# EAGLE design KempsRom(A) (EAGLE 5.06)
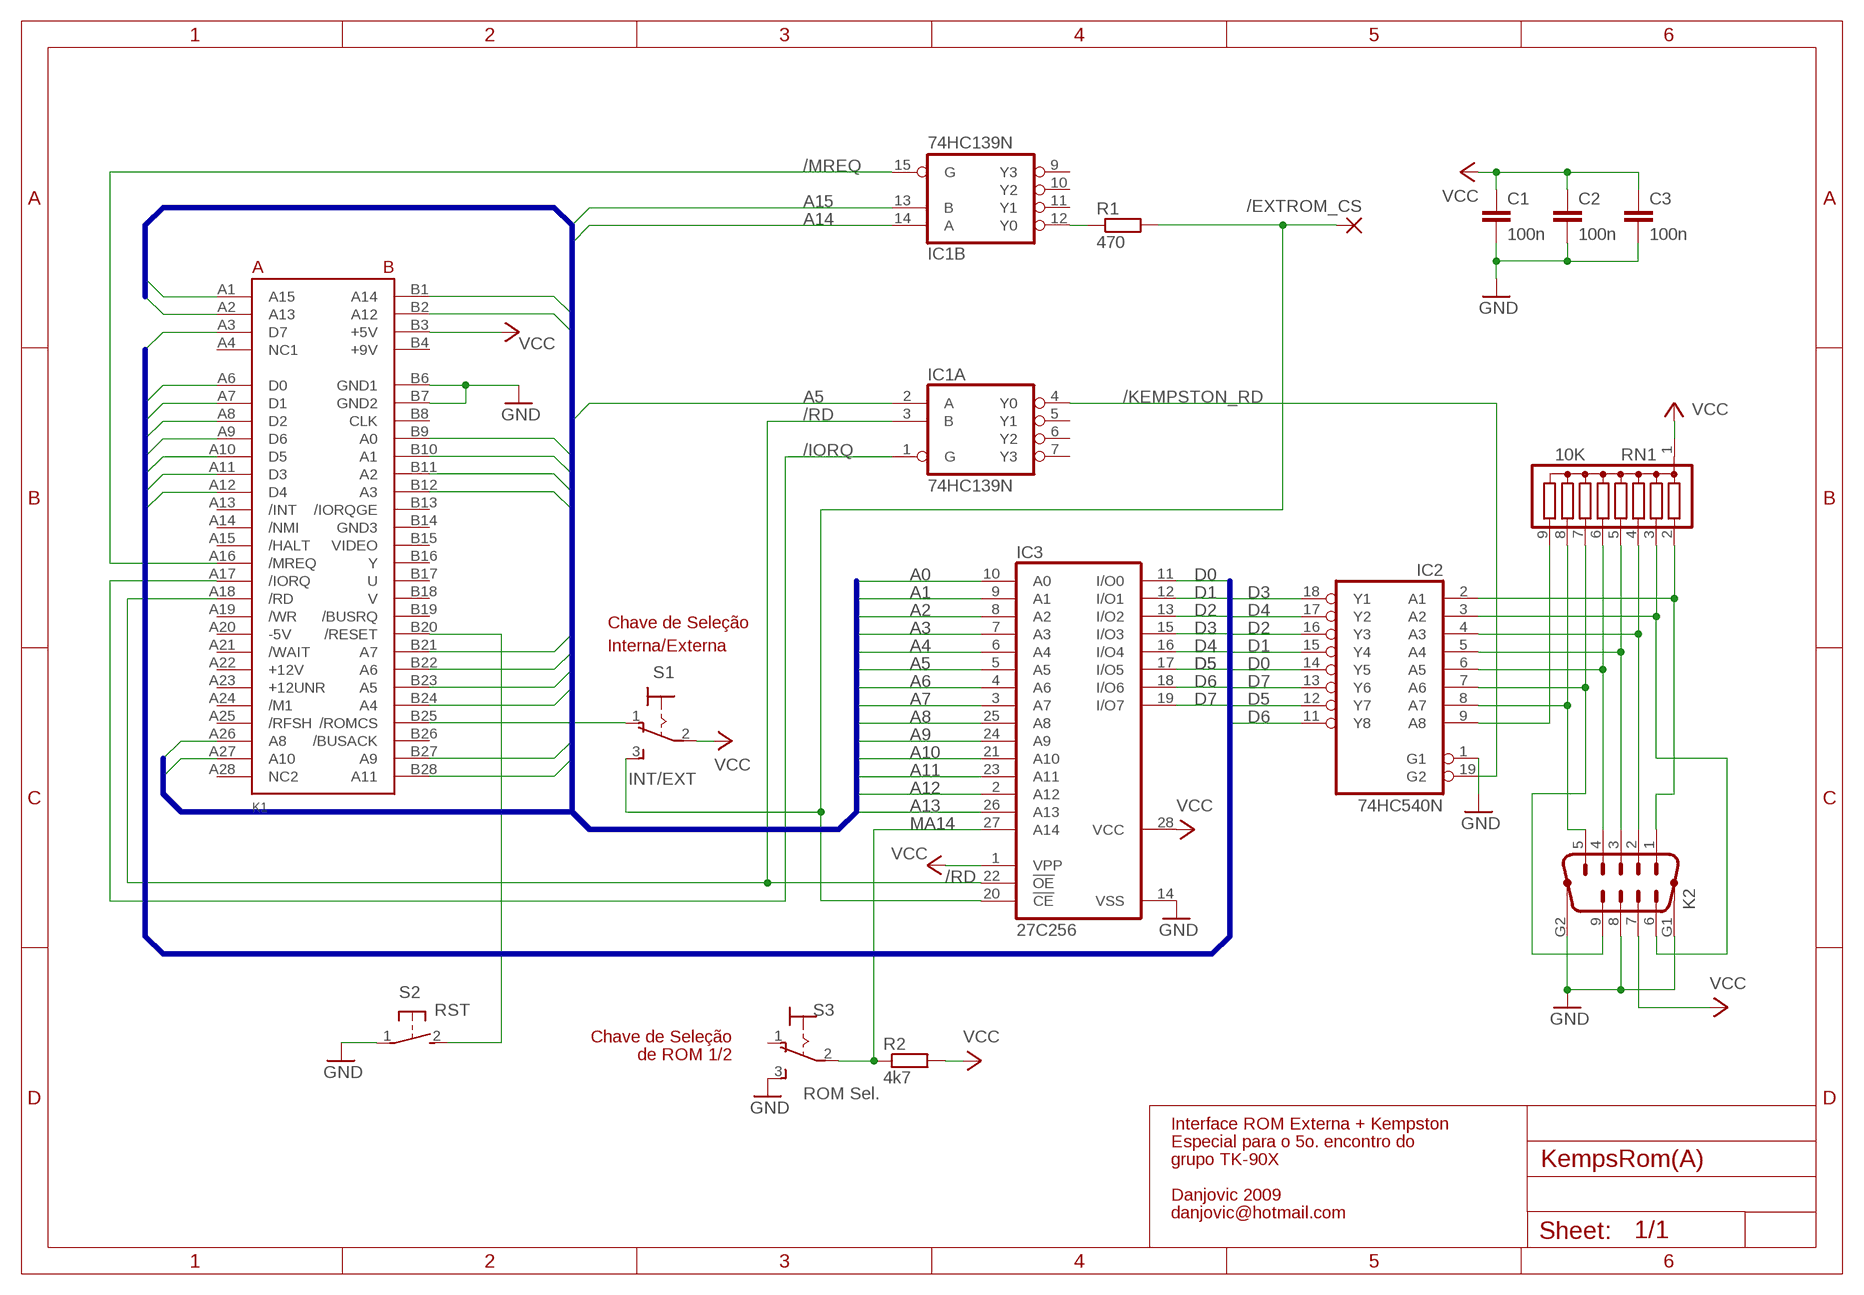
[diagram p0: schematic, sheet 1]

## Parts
/EXTROM_CS  1,6/0,8  [1,6/0,8]
C1  100n  C-EU050-025X075  [C050-025X075]
C2  100n  C-EU050-025X075  [C050-025X075]
C3  100n  C-EU050-025X075  [C050-025X075]
IC1  74HC139N  [DIL16]
IC2  74HC540N  [DIL20]
IC3  27C256  27C256AG  [DIL28-6]
K1  ZX-EDGE  [ZX-DIL]
K2  M09HP  [M09HP]
R1  470  R-EU_0204/7  [0204/7]
R2  4k7  R-EU_0204/7  [0204/7]
RN1  10K  G08R  [SIL9]
S1  INT/EXT  320-916  [320-916]
S2  RST  31-XX  [B3F-31XX]
S3  ROM Sel.  320-916  [320-916]

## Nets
/EXTROM_CS: /EXTROM_CS.1(P) IC3.20(!CE) R1.2 S1.3(S)
/IORQ: IC1.1(A:G) K1.A17(/IORQ)
/KEMPSTON_RD: IC1.4(A:Y0) IC2.19(G2)
/MREQ: IC1.15(B:G) K1.A16(/MREQ)
/RD: IC1.3(A:B) IC3.22(!OE) K1.A18(/RD)
/RESET: K1.B20(/RESET) S2.2(S)
/ROMCS: K1.B25(/ROMCS) S1.1(O)
A0: IC3.10(A0) K1.B9(A0)
A1: IC3.9(A1) K1.B10(A1)
A2: IC3.8(A2) K1.B11(A2)
A3: IC3.7(A3) K1.B12(A3)
A4: IC3.6(A4) K1.B24(A4)
A5: IC1.2(A:A) IC3.5(A5) K1.B23(A5)
A6: IC3.4(A6) K1.B22(A6)
A7: IC3.3(A7) K1.B21(A7)
A8: IC3.25(A8) K1.A26(A8)
A9: IC3.24(A9) K1.B27(A9)
A10: IC3.21(A10) K1.A27(A10)
A11: IC3.23(A11) K1.B28(A11)
A12: IC3.2(A12) K1.B2(A12)
A13: IC3.26(A13) K1.A2(A13)
A14: IC1.14(B:A) K1.B1(A14)
A15: IC1.13(B:B) K1.A1(A15)
D0: IC2.14(Y5) IC3.11(I/O0) K1.A6(D0)
D1: IC2.15(Y4) IC3.12(I/O1) K1.A7(D1)
D2: IC2.16(Y3) IC3.13(I/O2) K1.A8(D2)
D3: IC2.18(Y1) IC3.15(I/O3) K1.A11(D3)
D4: IC2.17(Y2) IC3.16(I/O4) K1.A12(D4)
D5: IC2.12(Y7) IC3.17(I/O5) K1.A10(D5)
D6: IC2.11(Y8) IC3.18(I/O6) K1.A9(D6)
D7: IC2.13(Y6) IC3.19(I/O7) K1.A3(D7)
GND: C1.2 C2.2 C3.2 IC2.1(G1) IC3.14(VSS) K1.B6(GND1) K1.B7(GND2) K2.8 K2.G1 K2.G2 S2.1(P) S3.3(S)
MA14: IC3.27(A14) R2.1 S3.2(P)
N$1: IC2.2(A1) K2.1 RN1.2
N$2: IC1.12(B:Y0) R1.1
N$4: IC2.3(A2) K2.6 RN1.3
N$5: IC2.4(A3) K2.2 RN1.4
N$6: IC2.5(A4) K2.3 RN1.5
N$7: IC2.6(A5) K2.4 RN1.6
N$8: IC2.7(A6) K2.9 RN1.7
N$9: IC2.8(A7) K2.5 RN1.8
N$10: IC2.9(A8) RN1.9
VCC: C1.1 C2.1 C3.1 IC3.1(VPP) IC3.28(VCC) K1.B3(+5V) K2.7 R2.2 RN1.1 S1.2(P)
Unconnected: IC1.5(A:Y1) IC1.6(A:Y2) IC1.7(A:Y3) IC1.9(B:Y3) IC1.10(B:Y2) IC1.11(B:Y1) K1.A4(NC1) K1.A13(/INT) K1.A14(/NMI) K1.A15(/HALT) K1.A19(/WR) K1.A20(-5V) K1.A21(/WAIT) K1.A24(/M1) K1.A25(/RFSH) K1.A28(NC2) K1.B8(CLK) K1.B13(/IORQGE) K1.B14(GND3) K1.B15(VIDEO) K1.B16(Y) K1.B17(U) K1.B18(V) K1.B19(/BUSRQ) K1.B26(/BUSACK) S3.1(O)

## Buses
A[0..15]
D[0..7]

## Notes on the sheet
- Chave de Seleção
- Interna/Externa
- Chave de Seleção
- de ROM 1/2
- Interface ROM Externa + Kempston
- Especial para o 5o. encontro do
- grupo TK-90X
- Danjovic 2009
- danjovic@hotmail.com

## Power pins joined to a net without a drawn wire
+9V: K1.B4(+9V)
+12UNR: K1.A23(+12UNR)
+12V: K1.A22(+12V)
GND: IC1.8(P:GND) IC2.10(GND)
VCC: IC1.16(P:VCC) IC2.20(VCC)

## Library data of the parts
/EXTROM_CS = wirepad:1,6/0,8: THROUGH-HOLE PAD
C1-C3 = rcl:C-EU: CAPACITOR, European symbol
IC1 = 74xx-eu:74*139: Dual 2-line to 4-line DECODER/DEMULTIPLEXER
IC2 = 74xx-eu:74*540: Octal BUFFER and LINE DRIVER, 3-state
IC3 = memory-hitachi:27C256AG: MEMORY
K1 = diversos2:ZX-EDGE: ZX Spectrum Rear edge connector
K2 = con-subd:M09HP: SUB-D
R1 R2 = rcl:R-EU_: RESISTOR, European symbol
RN1 = resistor-sil:G08R: SIL RESISTOR
S1 S3 = switch:320-916: TOGGLE SWITCH distributor RS Components
S2 = switch-omron:31-XX: OMRON SWITCH

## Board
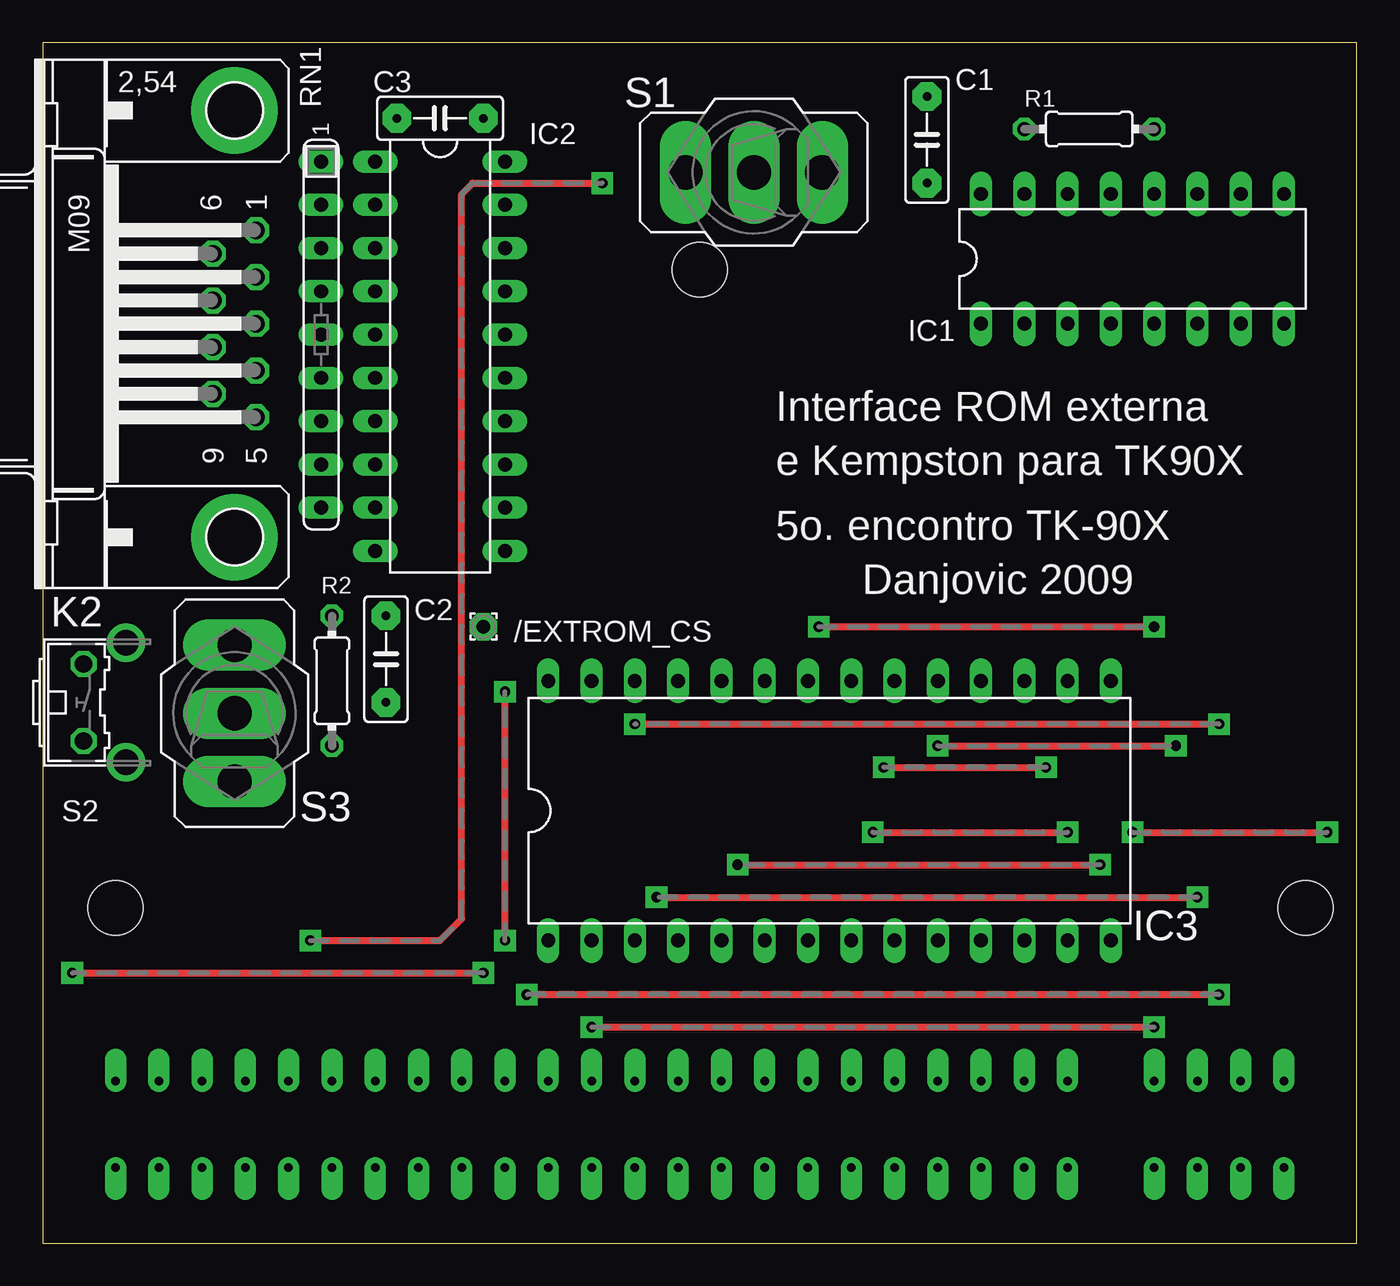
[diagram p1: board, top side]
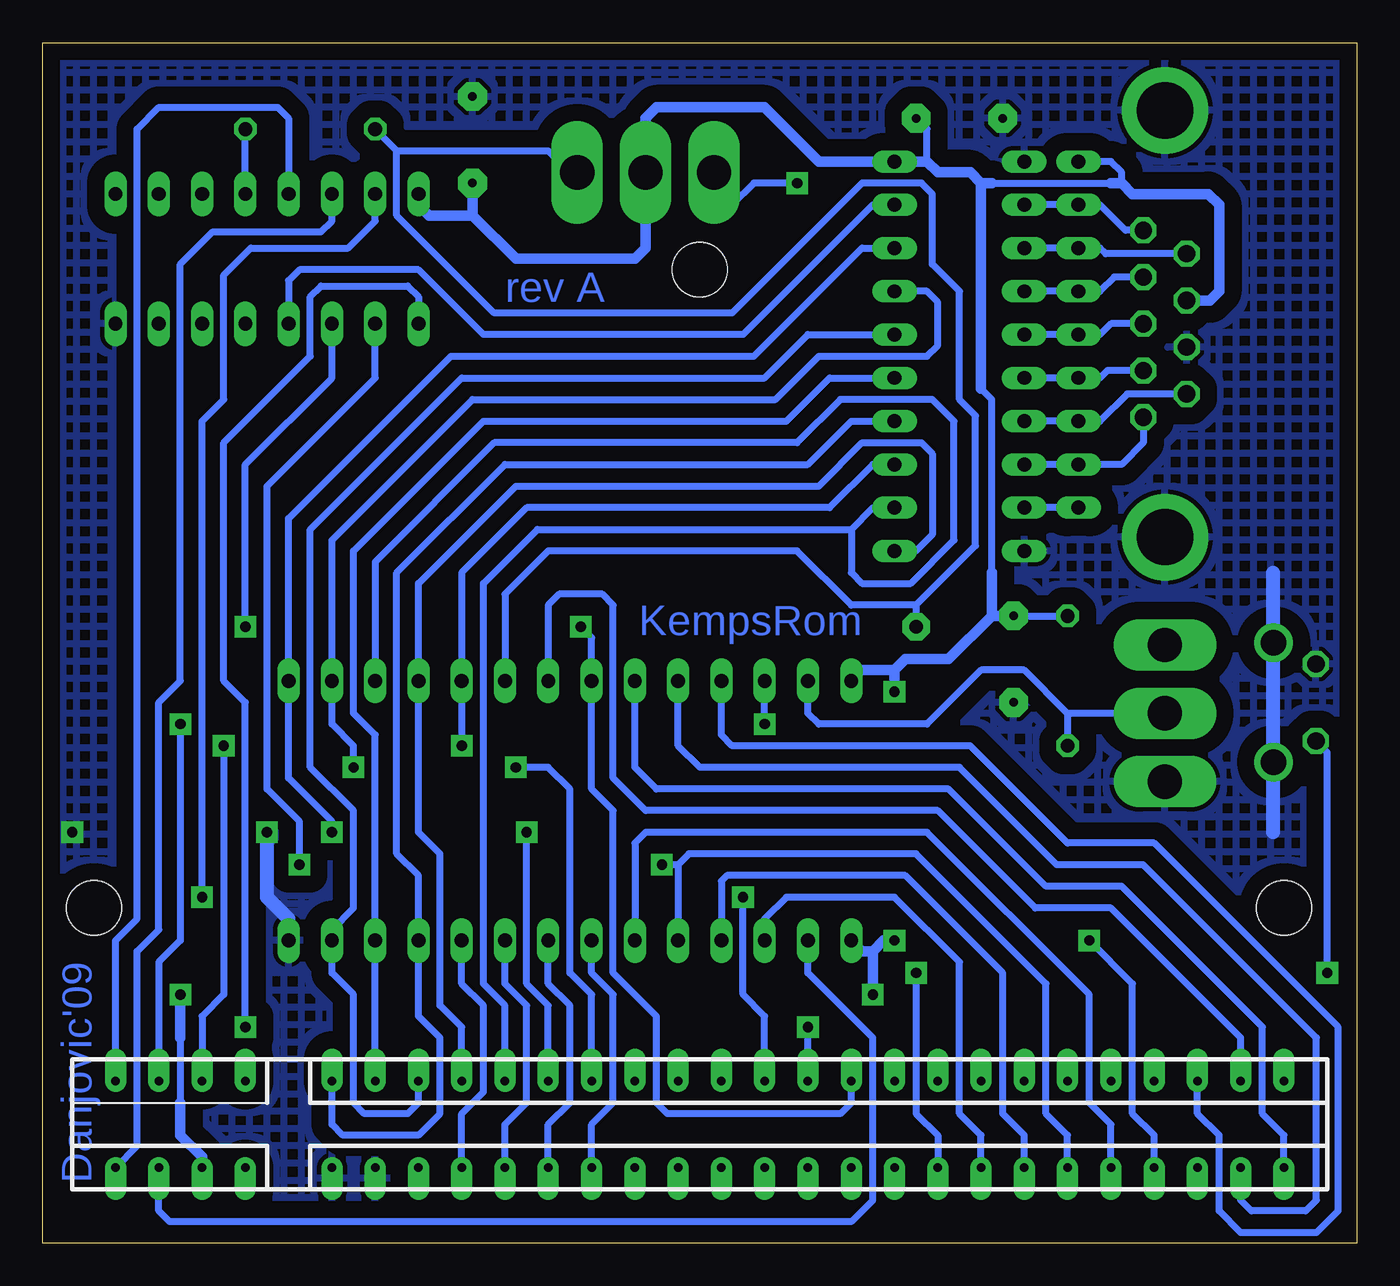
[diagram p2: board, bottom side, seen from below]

Size 77.14 x 70.47 mm. Coordinates in mm from the lower left corner, seen from the top.
Outline: 0,0 77.14,0 77.14,70.47 0,70.47 0,0
Copper layers (1*16): Top 0.035mm / dielectric 1.5mm / Bottom 0.035mm
Design rules "default": minimum track width 10mil, minimum drill 24mil, track to track 8mil, track to pad 8mil, pad to pad 8mil, via to via 8mil, smd to smd 8mil, copper to edge 40mil, drill to drill 8mil, minimum pad ring 10mil, minimum via ring 8mil, stop-mask expansion 4mil, vias tented up to drill 0mil, thermal gap 10mil
Holes 3.2 mm at 4.28,19.68 74.13,19.68 38.57,57.15

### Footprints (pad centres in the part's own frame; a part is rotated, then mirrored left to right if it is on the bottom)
1,6/0,8 = drill 0.813 pad 1.6 octagon: 1 0,0
C050-025X075 = drill 0.5 pad 1.676 octagon: 1 -2.54,0; 2 2.54,0
DIL16 = drill 0.813 long: 1 -8.89,-3.81; 2 -6.35,-3.81; 3 -3.81,-3.81; 4 -1.27,-3.81; 5 1.27,-3.81; 6 3.81,-3.81; 7 6.35,-3.81; 8 8.89,-3.81; 9 8.89,3.81; 10 6.35,3.81; 11 3.81,3.81; 12 1.27,3.81; 13 -1.27,3.81; 14 -3.81,3.81; 15 -6.35,3.81; 16 -8.89,3.81
DIL20 = drill 0.813 long: 1 -11.43,-3.81; 2 -8.89,-3.81; 3 -6.35,-3.81; 4 -3.81,-3.81; 5 -1.27,-3.81; 6 1.27,-3.81; 7 3.81,-3.81; 8 6.35,-3.81; 9 8.89,-3.81; 10 11.43,-3.81; 11 11.43,3.81; 12 8.89,3.81; 13 6.35,3.81; 14 3.81,3.81; 15 1.27,3.81; 16 -1.27,3.81; 17 -3.81,3.81; 18 -6.35,3.81; 19 -8.89,3.81; 20 -11.43,3.81
DIL28-6 = drill 0.813 long: 1 -16.51,-7.62; 2 -13.97,-7.62; 3 -11.43,-7.62; 4 -8.89,-7.62; 5 -6.35,-7.62; 6 -3.81,-7.62; 7 -1.27,-7.62; 8 1.27,-7.62; 9 3.81,-7.62; 10 6.35,-7.62; 11 8.89,-7.62; 12 11.43,-7.62; 13 13.97,-7.62; 14 16.51,-7.62; 15 16.51,7.62; 16 13.97,7.62; 17 11.43,7.62; 18 8.89,7.62; 19 6.35,7.62; 20 3.81,7.62; 21 1.27,7.62; 22 -1.27,7.62; 23 -3.81,7.62; 24 -6.35,7.62; 25 -8.89,7.62; 26 -11.43,7.62; 27 -13.97,7.62; 28 -16.51,7.62
ZX-DIL = drill 0.5 pad 1.27 offset: A1 2.54,33.02; A2 2.54,30.48; A3 2.54,27.94; A4 2.54,25.4; A6 2.54,20.32; A7 2.54,17.78; A8 2.54,15.24; A9 2.54,12.7; A10 2.54,10.16; A11 2.54,7.62; A12 2.54,5.08; A13 2.54,2.54; A14 2.54,0; A15 2.54,-2.54; A16 2.54,-5.08; A17 2.54,-7.62; A18 2.54,-10.16; A19 2.54,-12.7; A20 2.54,-15.24; A21 2.54,-17.78; A22 2.54,-20.32; A23 2.54,-22.86; A24 2.54,-25.4; A25 2.54,-27.94; A26 2.54,-30.48; A27 2.54,-33.02; A28 2.54,-35.56; B1 -2.54,33.02; B2 -2.54,30.48; B3 -2.54,27.94; B4 -2.54,25.4; B6 -2.54,20.32; B7 -2.54,17.78; B8 -2.54,15.24; B9 -2.54,12.7; B10 -2.54,10.16; B11 -2.54,7.62; B12 -2.54,5.08; B13 -2.54,2.54; B14 -2.54,0; B15 -2.54,-2.54; B16 -2.54,-5.08; B17 -2.54,-7.62; B18 -2.54,-10.16; B19 -2.54,-12.7; B20 -2.54,-15.24; B21 -2.54,-17.78; B22 -2.54,-20.32; B23 -2.54,-22.86; B24 -2.54,-25.4; B25 -2.54,-27.94; B26 -2.54,-30.48; B27 -2.54,-33.02; B28 -2.54,-35.56
M09HP = drill 1.016 octagon: 1 -5.486,1.27; 2 -2.743,1.27; 3 0,1.27; 4 2.743,1.27; 5 5.486,1.27; 6 -4.115,-1.27; 7 -1.372,-1.27; 8 1.372,-1.27; 9 4.115,-1.27 | drill 3.302 pad 5.08 round: G1 -12.522,0; G2 12.522,0
0204/7 = drill 0.813 octagon: 1 -3.81,0; 2 3.81,0
SIL9 = drill 0.813 long: 1 -10.16,0; 2 -7.62,0; 3 -5.08,0; 4 -2.54,0; 5 0,0; 6 2.54,0; 7 5.08,0; 8 7.62,0; 9 10.16,0
320-916 = drill 2.007 long: 1 0,4.013; 2 0,0; 3 0,-4.013
B3F-31XX = drill 1.016 octagon: 1 -2.261,-1.245; 2 2.261,-1.245 | drill 1.499 pad 2.159 round: 3 -3.505,1.245; 4 3.505,1.245

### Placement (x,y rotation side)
/EXTROM_CS  25.87,36.19 0 top
C1  51.91,64.77 90 top
C2  20.16,34.29 270 top
C3  23.33,66.03 180 top
IC1  63.97,57.78 0 top
IC2  23.33,52.07 270 top
IC3  46.19,25.39 0 top
K1  39.84,6.98 90 bottom
K2  11.26,53.97 270 top
R1  61.43,65.4 180 top
R2  16.98,33.02 90 top
RN1  16.34,53.34 270 top
S1  41.75,62.86 90 top
S2  3.64,31.74 270 top
S3  11.26,31.11 0 top

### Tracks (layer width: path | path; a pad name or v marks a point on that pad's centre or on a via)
/EXTROM_CS
  Bottom 0.406: IC3.20 50,38.1 47.46,40.64 32.86,40.64 29.68,37.46 25.87,37.46 | 25.87,37.46 22.38,40.95 22.38,48.57 23.33,49.53 23.33,55.88 24.92,57.46 24.92,61.59 25.55,62.23 29.05,62.23 36.66,54.61 50.63,54.61 56.35,60.32 56.35,64.13 | 56.35,64.13 R1.2 | 56.35,64.13 47.46,64.13 45.76,62.43 S1.3 | 25.87,37.46 /EXTROM_CS.1
/IORQ  (via drill 0.6 pad 1.27)
  Top 0.406: v32.22,12.7 v65.24,12.7
  Bottom 0.406: K1.A17 v32.22,12.7 | v65.24,12.7 65.24,31.74 66.51,33.02 66.51,46.98 61.43,52.07 61.43,55.56 60.79,56.19 55.72,56.19 55.08,55.56 IC1.1
/KEMPSTON_RD
  Bottom 0.406: IC1.4 62.7,56.51 62.07,57.15 55.08,57.15 51.27,53.34 36.03,53.34 28.41,60.96 IC2.19
/MREQ  (via drill 0.6 pad 1.27)
  Top 0.406: v36.03,20.31 v67.78,20.31
  Bottom 0.406: K1.A16 34.76,13.33 36.03,14.6 v36.03,20.31 | v67.78,20.31 67.78,48.26 66.51,49.53 66.51,56.83 64.92,58.41 59.21,58.41 57.62,60 IC1.15
/RD  (via drill 0.6 pad 1.27)
  Top 0.406: v45.55,36.19 v65.24,36.19
  Bottom 0.406: 29.68,10.16 K1.A18 29.68,8.25 30.32,7.62 40.48,7.62 41.11,8.25 41.11,13.33 43.65,15.87 43.65,25.39 44.92,26.66 IC3.22 44.92,35.55 v45.55,36.19 | IC1.3 60.16,50.8 65.24,45.72 v65.24,36.19
/RESET  (via drill 0.6 pad 1.27)
  Top 0.406: v1.74,15.87 v25.87,15.87
  Bottom 0.406: S2.2 1.74,28.82 v1.74,15.87 | v25.87,15.87 25.87,7.62 24.6,6.34 K1.B20
/ROMCS  (via drill 0.6 pad 1.27)
  Top 0.406: v15.71,17.77 23.33,17.77 24.6,19.04 24.6,61.59 25.23,62.23 v32.86,62.23
  Bottom 0.406: K1.B25 11.9,6.34 13.17,7.62 13.17,15.24 v15.71,17.77 | v32.86,62.23 35.4,62.23 36.66,60.96 37.94,60.96 37.73,61.16 S1.1
A0
  Bottom 0.406: K1.B9 52.54,7.62 51.27,8.89 51.27,13.97 52.54,15.24 IC3.10
A1
  Bottom 0.406: K1.B10 50,6.98 48.73,8.25 48.73,13.97 50,15.24 IC3.9
A2
  Bottom 0.406: K1.B11 47.46,6.98 46.19,8.25 46.19,13.97 47.46,15.24 IC3.8
A3
  Bottom 0.406: K1.B12 44.92,6.98 43.65,8.25 43.65,14.6 44.92,15.87 IC3.7
A4
  Bottom 0.406: K1.B24 14.44,6.98 15.71,8.25 15.71,14.6 25.23,24.12 41.75,24.12 42.38,23.49 IC3.6
A5  (via drill 0.6 pad 1.27)
  Top 0.406: v40.79,22.22 v62.07,22.22
  Bottom 0.406: K1.B23 16.98,6.34 18.25,7.62 18.25,15.24 25.87,22.86 39.2,22.86 39.84,22.22 | IC1.2 57.62,50.8 63.97,44.45 63.97,26.66 62.07,24.76 v62.07,22.22 | 39.84,22.22 IC3.5 | 39.84,22.22 v40.79,22.22
A6
  Bottom 0.406: IC3.4 37.3,21.27 36.98,21.58 26.51,21.58 20.79,15.87 20.79,7.62 19.52,6.34 K1.B22
A7
  Bottom 0.406: K1.B21 22.06,6.34 23.33,7.62 23.33,16.5 27.14,20.31 33.49,20.31 34.76,19.04 IC3.3
A8
  Bottom 0.406: K1.A26 9.36,7.62 8.09,6.34 8.09,1.9 6.82,0.63 2.38,0.63 1.11,1.9 1.11,12.7 11.9,23.49 16.98,23.49 22.7,29.2 36.66,29.2 37.3,29.84 IC3.25
A9
  Bottom 0.406: IC3.24 39.84,29.2 38.57,27.93 23.33,27.93 17.62,22.22 12.53,22.22 2.38,12.06 2.38,2.54 3.01,1.9 6.19,1.9 6.82,2.54 K1.B27
A10
  Bottom 0.406: K1.A27 6.82,12.06 14.44,19.68 18.88,19.68 24.6,25.39 41.75,25.39 43.65,27.3 43.65,37.46 44.29,38.1 46.83,38.1 47.46,37.46 IC3.21
A11
  Bottom 0.406: IC3.23 42.38,27.93 41.11,26.66 23.96,26.66 18.25,20.95 13.8,20.95 5.55,12.7 5.55,7.62 4.28,6.34 K1.B28
A12
  Bottom 0.406: K1.B2 70.32,1.9 69.68,1.27 29.68,1.27 28.41,2.54 28.41,12.06 32.22,15.87 IC3.2
A13  (via drill 0.6 pad 1.27)
  Top 0.406: v34.76,30.47 v69.05,30.47
  Bottom 0.406: v69.05,30.47 69.05,17.77 70.32,16.5 K1.A2 | v34.76,30.47 IC3.26
A14
  Bottom 0.406: K1.B1 71.59,5.71 71.59,17.14 70.32,18.41 70.32,31.74 69.05,33.02 69.05,57.46 67.14,59.37 60.79,59.37 60.16,60 IC1.14
A15
  Bottom 0.406: K1.A1 72.86,17.77 71.59,19.04 71.59,65.4 70.32,66.67 63.34,66.67 62.7,66.03 IC1.13
D0
  Bottom 0.406: IC2.14 29.68,48.26 32.22,45.72 50,45.72 56.35,39.37 56.35,22.86 55.08,21.58 IC3.11 55.08,13.33 53.81,12.06 53.81,7.62 55.08,6.34 59.52,6.34 60.16,6.98 K1.A6
D1
  Bottom 0.406: IC2.15 30.95,50.8 33.49,48.26 51.27,48.26 58.89,40.64 58.89,31.11 57.62,29.84 IC3.12 K1.A7
D2
  Bottom 0.406: IC2.16 32.22,53.34 34.76,50.8 52.54,50.8 61.43,41.91 61.43,27.93 58.89,25.39 58.89,19.68 60.16,18.41 IC3.13 60.16,15.87 58.89,14.6 58.89,8.25 58.26,7.62 55.72,7.62 55.08,8.25 K1.A8
D3  (via drill 0.6 pad 1.27)
  Top 0.406: v48.73,24.12 v60.16,24.12
  Bottom 0.406: IC2.18 29.05,58.41 35.4,52.07 53.18,52.07 62.7,42.54 IC3.15 62.7,27.3 60.16,24.76 v60.16,24.12 | K1.A11 47.46,13.97 48.73,15.24 v48.73,24.12
D4  (via drill 0.6 pad 1.27)
  Top 0.406: v49.37,27.93 v58.89,27.93
  Bottom 0.406: IC2.17 25.23,55.88 24.6,55.24 24.6,52.7 25.23,52.07 31.59,52.07 34.12,49.53 51.91,49.53 60.16,41.27 IC3.16 60.16,30.47 58.89,29.2 v58.89,27.93 | K1.A12 44.92,14.6 46.19,15.87 46.19,26.66 47.46,27.93 v49.37,27.93
D5
  Bottom 0.406: 29.68,41.91 29.68,39.37 29.05,38.73 26.19,38.73 23.65,41.27 23.65,48.26 24.92,49.53 30.32,49.53 32.86,46.98 50.63,46.98 57.62,40 IC3.17 | K1.A10 50,13.97 51.27,15.24 51.27,38.73 48.09,41.91 29.68,41.91 | 29.68,41.91 28.41,43.18 IC2.12
D6
  Bottom 0.406: IC2.11 25.87,40.64 24.92,41.59 24.92,46.35 25.55,46.98 29.05,46.98 31.59,44.45 49.37,44.45 55.08,38.73 IC3.18 55.08,24.12 53.81,22.86 53.81,13.97 52.54,12.7 K1.A9
D7  (via drill 0.6 pad 1.27)
  Top 0.406: v52.54,29.2 v66.51,29.2
  Bottom 0.406: IC2.13 28.41,45.72 30.95,43.18 48.73,43.18 52.54,39.37 IC3.19 v52.54,29.2 | v66.51,29.2 66.51,14.6 67.78,13.33 K1.A3
GND  (via drill 0.6 pad 1.27)
  Top 0.406: v63.97,24.12 v75.4,24.12
  Bottom 0.406: IC3.14 62.7,19.04
  Bottom 0.813: 4.91,24.12 4.91,39.37 | v63.97,24.12 63.97,20.31 62.7,19.04
  pour Bottom (isolate 1.016, hatched): 77.94,71.11 77.94,-0.64 -0.8,-0.64 -0.8,71.11
MA14
  Bottom 0.406: IC3.27 32.22,31.11 31.59,30.47 25.23,30.47 22.06,33.65 19.52,33.65 16.98,31.11 | S3.2 16.98,31.11 | 16.98,31.11 R2.1
N$1
  Bottom 0.406: K2.1 13.58,59.46 15.08,60.96 RN1.2 IC2.2
N$2
  Bottom 0.406: IC1.12 R1.1
N$4
  Bottom 0.406: K2.6 14.74,58.09 15.08,58.41 RN1.3 IC2.3
N$5
  Bottom 0.406: K2.2 14.24,56.71 15.08,55.88 RN1.4 IC2.4
N$6
  Bottom 0.406: K2.3 14.44,53.97 15.08,53.34 RN1.5 IC2.5
N$7
  Bottom 0.406: K2.4 14.64,51.23 15.08,50.8 RN1.6 IC2.6
N$8
  Bottom 0.406: K2.9 13.47,49.86 15.08,48.26 RN1.7 IC2.7
N$9
  Bottom 0.406: K2.5 12.53,46.98 13.8,45.72 RN1.8 IC2.8
N$10
  Bottom 0.406: RN1.9 IC2.9
VCC  (via drill 0.6 pad 1.27)
  Top 0.406: v27.14,17.77 v27.14,32.38 | v28.41,14.6 v69.05,14.6
  Bottom 0.406: 13.8,62.23 13.8,62.86 14.44,63.5 RN1.1 | 55.08,60.96 IC1.16 | 69.05,12.06 69.05,8.25 | 22.06,50.16 21.42,49.53 21.42,39.37 | C3.1 25.23,65.4 25.23,63.5 | C2.1 R2.2 | 21.42,62.23 14.44,62.23
  Bottom 0.61: K2.7 8.62,55.34 8.09,55.88 8.09,60.96 8.72,61.59 13.17,61.59 13.8,62.23 14.44,62.23 | 22.06,62.23 22.7,62.86 24.6,62.86 25.23,63.5 IC2.20 31.59,63.5 34.76,66.67 41.11,66.67 41.75,66.03 S1.2 41.75,58.41 42.38,57.78 49.37,57.78 51.91,60.32 | 22.06,62.23 21.42,62.23 | IC3.28 29.68,33.65 27.14,33.65 | 51.91,60.32 54.45,60.32 55.08,60.96 | 51.91,60.32 C1.1 | 27.14,33.65 26.51,34.29 23.96,34.29 21.42,36.83 | K1.B3 67.78,5.08 69.05,6.34 69.05,8.25 | 22.06,50.16 22.06,62.23 | v27.14,32.38 27.14,33.65 | v28.41,14.6 28.41,17.14 | 28.41,17.14 29.05,17.14 IC3.1 | v27.14,17.77 27.77,17.77 28.41,17.14 | 21.42,36.83 C2.1 | v69.05,14.6 69.05,12.06 | 21.42,36.83 21.42,39.37
(copper drawn outside any net)
  shapes: Bottom circle x6

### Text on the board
Bottom: rev A | KempsRom | Danjovic'09
tPlace: Interface ROM externa | e Kempston para TK90X | 5o. encontro TK-90X | Danjovic 2009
